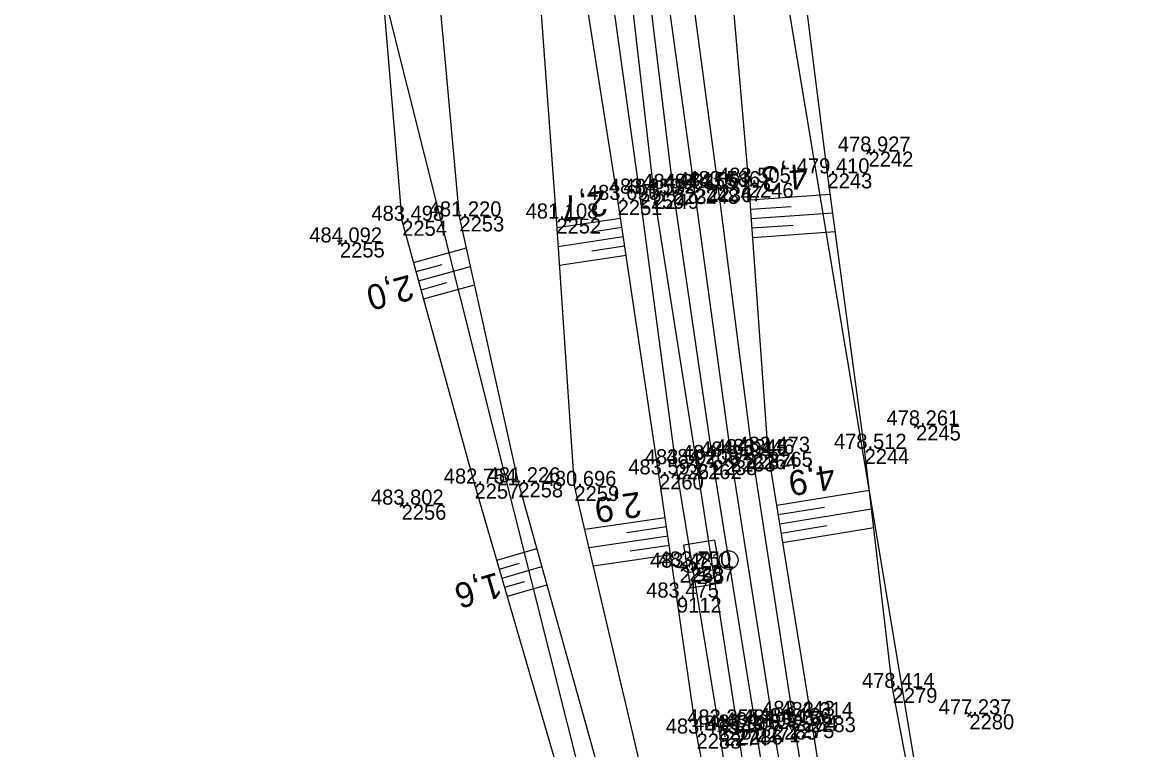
# Model space of a CAD drawing. Extents: x -1234191 to 23050, y -1290331 to -741191.
# Drawn here: x -865097.3 to -865009.1, y -1108134.3 to -1108076.3 of the extents above; entities that cross this region are included whole.
import ezdxf

# ---------------------------------------------------------------- set-up
doc = ezdxf.new("R2010")
doc.units = 0
for name, color, linetype in [('Vrstva 1', 7, 'Continuous'), ('Vrstva 4', 7, 'Continuous'), ('Vrstva 48', 7, 'Continuous'), ('Vrstva 49', 7, 'Continuous'), ('Vrstva 53', 7, 'Continuous'), ('Vrstva 60', 7, 'Continuous'), ('Vrstva 61', 7, 'Continuous'), ('Vrstva 7', 7, 'Continuous')]:
    doc.layers.add(name, color=color, linetype=linetype)

msp = doc.modelspace()

# ---------------------------------------------------------------- linework, layer by layer
at = {"layer": 'Vrstva 1'}
msp.add_lwpolyline([(-865043.737, -1107938.353), (-865046.293, -1107957.671), (-865048.446, -1107977.08), (-865049.959, -1107996.714), (-865050.615, -1108021.454), (-865049.803, -1108046.852), (-865047.929, -1108068.568), (-865045.362, -1108089.589), (-865042.206, -1108111.201), (-865038.777, -1108132.509), (-865035.865, -1108150.791), (-865033.081, -1108169.348), (-865030.656, -1108187.291), (-865028.588, -1108206.453)], dxfattribs=at)
at = {"layer": 'Vrstva 4'}
for points in [[(-865046.838, -1107937.897), (-865049.766, -1107957.319), (-865052.264, -1107976.931), (-865053.043, -1107995.978), (-865053.508, -1108021.506), (-865052.913, -1108047.234), (-865050.973, -1108068.777), (-865048.028, -1108089.964), (-865045.164, -1108111.536), (-865041.768, -1108132.286), (-865038.97, -1108150.895), (-865036.086, -1108170.021), (-865033.638, -1108187.61), (-865031.529, -1108206.589)], [(-865030.043, -1108206.47), (-865032.088, -1108187.414), (-865034.573, -1108169.592), (-865037.31, -1108151.168), (-865040.185, -1108132.688), (-865043.456, -1108111.522), (-865046.855, -1108089.973), (-865049.336, -1108068.397), (-865051.315, -1108046.93), (-865052.165, -1108021.586), (-865051.499, -1107996.614), (-865050.047, -1107977.053), (-865047.911, -1107957.568), (-865045.268, -1107938.168)], [(-865042.248, -1107938.487), (-865044.796, -1107958.232), (-865047.08, -1107977.245), (-865048.482, -1107996.693), (-865048.879, -1108021.383), (-865048.168, -1108046.692), (-865046.633, -1108068.21), (-865043.659, -1108089.569), (-865040.741, -1108110.916), (-865037.386, -1108132.285), (-865034.227, -1108151.033), (-865031.45, -1108169.147), (-865029.088, -1108187.033), (-865027.037, -1108206.108)], [(-865026.077, -1108206.153), (-865027.957, -1108186.689), (-865030.267, -1108169.011), (-865032.717, -1108150.399), (-865035.8, -1108131.6), (-865039.027, -1108110.722), (-865041.763, -1108089.361), (-865044.61, -1108068.082), (-865046.259, -1108046.615), (-865047.844, -1108021.319), (-865047.118, -1107996.694), (-865045.313, -1107977.555), (-865043.041, -1107958.531), (-865041.079, -1107938.659)]]:
    msp.add_lwpolyline(points, dxfattribs=at)
at = {"layer": 'Vrstva 48'}
for p, q in [((-865039.214, -1108090.455), (-865032.815, -1108089.998)), ((-865039.16, -1108091.203), (-865035.937, -1108090.973)), ((-865049.552, -1108091.931), (-865054.61, -1108092.693)), ((-865039.107, -1108091.951), (-865032.614, -1108091.488)), ((-865049.44, -1108092.673), (-865052, -1108093.058)), ((-865039.054, -1108092.699), (-865035.784, -1108092.466)), ((-865039, -1108093.447), (-865032.413, -1108092.977)), ((-865049.329, -1108093.414), (-865054.509, -1108094.194)), ((-865066.047, -1108095.453), (-865061.836, -1108094.293)), ((-865049.217, -1108094.156), (-865051.837, -1108094.55)), ((-865065.848, -1108096.176), (-865063.761, -1108095.601)), ((-865049.105, -1108094.897), (-865054.407, -1108095.696)), ((-865065.649, -1108096.899), (-865061.512, -1108095.76)), ((-865065.45, -1108097.622), (-865063.4, -1108097.058)), ((-865065.251, -1108098.345), (-865061.187, -1108097.226)), ((-865037.089, -1108114.803), (-865029.69, -1108113.603)), ((-865036.968, -1108115.544), (-865033.285, -1108114.946)), ((-865036.848, -1108116.284), (-865029.515, -1108115.094)), ((-865045.974, -1108115.796), (-865052.406, -1108116.735)), ((-865045.866, -1108116.538), (-865049.049, -1108117.003)), ((-865036.728, -1108117.024), (-865033.078, -1108116.432)), ((-865036.608, -1108117.765), (-865029.34, -1108116.586)), ((-865045.758, -1108117.281), (-865052.06, -1108118.2)), ((-865059.415, -1108119.178), (-865056.226, -1108118.247)), ((-865045.649, -1108118.023), (-865048.768, -1108118.478)), ((-865059.205, -1108119.898), (-865057.615, -1108119.434)), ((-865045.541, -1108118.765), (-865051.714, -1108119.666)), ((-865058.995, -1108120.618), (-865055.822, -1108119.692)), ((-865058.785, -1108121.338), (-865057.203, -1108120.876)), ((-865058.575, -1108122.058), (-865055.419, -1108121.137))]:
    msp.add_line(p, q, dxfattribs=at)
at = {"layer": 'Vrstva 49'}
for p, q in [((-865029.956, -1108086.455), (-865029.562, -1108086.763)), ((-865029.605, -1108086.412), (-865029.913, -1108086.806)), ((-865072.125, -1108093.705), (-865071.725, -1108094.003)), ((-865071.776, -1108093.654), (-865072.074, -1108094.054)), ((-865026.174, -1108108.29), (-865025.774, -1108108.588)), ((-865025.825, -1108108.239), (-865026.123, -1108108.639)), ((-865067.208, -1108114.608), (-865066.808, -1108114.906)), ((-865066.859, -1108114.557), (-865067.157, -1108114.957)), ((-865021.917, -1108131.325), (-865021.513, -1108131.619)), ((-865021.568, -1108131.27), (-865021.862, -1108131.674))]:
    msp.add_line(p, q, dxfattribs=at)
for points in [[(-865038.408, -1108186.181), (-865041.746, -1108175.265), (-865044.691, -1108155.296), (-865047.949, -1108135.607), (-865053.225, -1108113.267), (-865054.66, -1108091.943), (-865057.044, -1108059.317), (-865058.119, -1108048.868), (-865057.644, -1108021.123), (-865054.263, -1107996.365), (-865056.749, -1107976.312), (-865054.648, -1107957.542), (-865051.936, -1107936.756), (-865049.607, -1107917.984), (-865043.54, -1107878.327), (-865039.549, -1107861.727), (-865037.736, -1107845.055), (-865035.72, -1107829.325), (-865034.421, -1107813.61), (-865032.052, -1107796.735)], [(-865034.146, -1108185.382), (-865037.046, -1108170.203), (-865039.927, -1108151.218), (-865043.483, -1108133.01), (-865045.045, -1108122.164), (-865046.478, -1108112.344), (-865049.773, -1108090.463), (-865053.139, -1108069.022), (-865054.473, -1108047.375), (-865054.693, -1108021.243), (-865053.043, -1107995.978), (-865054.238, -1107976.976), (-865052.278, -1107956.977), (-865049.221, -1107937.193), (-865046.661, -1107918.236), (-865041.022, -1107878.425), (-865038.372, -1107862.082), (-865035.549, -1107845.348), (-865033.675, -1107829.555), (-865032.544, -1107813.589), (-865032.052, -1107796.735)], [(-865027.314, -1108184.355), (-865028.865, -1108168.738), (-865031.481, -1108150.159), (-865034.349, -1108131.694), (-865037.78, -1108110.54), (-865039.311, -1108089.092), (-865041.221, -1108067.079), (-865043.599, -1108046.805), (-865045.807, -1108021.331), (-865044.651, -1107996.201), (-865043.03, -1107977.831), (-865039.347, -1107959.35), (-865039.085, -1107938.119), (-865035.812, -1107919.001), (-865032.986, -1107893.483), (-865031.863, -1107879.382), (-865029.668, -1107863.423), (-865027.176, -1107846.896), (-865024.906, -1107830.539), (-865024.039, -1107813.771)], [(-865019.875, -1108184.12), (-865021.465, -1108167.421), (-865024.084, -1108149.374), (-865027.839, -1108129.369), (-865030.077, -1108110.307), (-865033.038, -1108088.344), (-865036.235, -1108062.921), (-865039.934, -1108046.29), (-865040.857, -1108022.088), (-865040.118, -1107996.004), (-865034.143, -1107980.294), (-865031.197, -1107960.331), (-865031.075, -1107928.571), (-865026.963, -1107900.752), (-865024.03, -1107878.592), (-865025.677, -1107865.45), (-865023.82, -1107848.157), (-865021.111, -1107832.183), (-865024.039, -1107813.771)], [(-865040.578, -1108188.523), (-865043.492, -1108176.04), (-865049.794, -1108152.178), (-865053.739, -1108138.634), (-865061.194, -1108113.081), (-865066.964, -1108092.124), (-865069.309, -1108064.185), (-865068.563, -1108046.185), (-865067.744, -1108018.452), (-865059.984, -1107995.159), (-865059.286, -1107975.697), (-865057.805, -1107956.237), (-865055.339, -1107936.975)], [(-865041.746, -1108175.265), (-865047.405, -1108151.931), (-865050.888, -1108137.362), (-865057.697, -1108112.978), (-865062.394, -1108091.777), (-865065.031, -1108062.839), (-865062.023, -1108047.253), (-865061.588, -1108018.947), (-865057.606, -1107991.29)]]:
    msp.add_lwpolyline(points, dxfattribs=at)
at = {"layer": 'Vrstva 53'}
for points in [[(-865097.28, -1108650.63), (-865077.79, -1108523.9), (-865062.58, -1108401.69), (-865048.74, -1108345.61), (-865033.548, -1108273.797), (-865036.719, -1108231.242), (-865042.497, -1108177.09), (-865069.37, -1108070.21), (-865060.755, -1107948.38), (-865040.047, -1107836.105), (-865031.84, -1107728.7), (-865056.26, -1107614.01)], [(-865004.69, -1107700.09), (-865003.06, -1107712.548), (-865020.95, -1107733.574), (-865021.38, -1107803.91), (-865041.945, -1107946.278), (-865044.86, -1108022.805), (-865018.158, -1108183.051), (-865018.752, -1108239.984), (-865026.02, -1108333.53), (-865033.42, -1108388.81), (-865018.239, -1108387.767), (-865021.853, -1108424.716), (-865038.93, -1108425.11), (-865057.34, -1108498.15), (-865069.183, -1108569.747)]]:
    msp.add_lwpolyline(points, dxfattribs=at)
at = {"layer": 'Vrstva 60'}
for p, q in [((-865029.759, -1108086.609), (-865029.759, -1108086.609)), ((-865033.038, -1108088.344), (-865033.038, -1108088.344)), ((-865042.613, -1108089.438), (-865042.613, -1108089.438)), ((-865041.763, -1108089.361), (-865041.763, -1108089.361)), ((-865039.311, -1108089.092), (-865039.311, -1108089.092)), ((-865048.028, -1108089.964), (-865048.028, -1108089.964)), ((-865046.855, -1108089.973), (-865046.855, -1108089.973)), ((-865045.362, -1108089.589), (-865045.362, -1108089.589)), ((-865043.659, -1108089.569), (-865043.659, -1108089.569)), ((-865049.773, -1108090.463), (-865049.773, -1108090.463)), ((-865066.964, -1108092.124), (-865066.964, -1108092.124)), ((-865062.394, -1108091.777), (-865062.394, -1108091.777)), ((-865054.66, -1108091.943), (-865054.66, -1108091.943)), ((-865071.925, -1108093.854), (-865071.925, -1108093.854)), ((-865025.974, -1108108.439), (-865025.974, -1108108.439)), ((-865037.78, -1108110.54), (-865037.78, -1108110.54)), ((-865030.077, -1108110.307), (-865030.077, -1108110.307)), ((-865045.164, -1108111.536), (-865045.164, -1108111.536)), ((-865043.456, -1108111.522), (-865043.456, -1108111.522)), ((-865042.206, -1108111.201), (-865042.206, -1108111.201)), ((-865040.741, -1108110.916), (-865040.741, -1108110.916)), ((-865039.55, -1108110.739), (-865039.55, -1108110.739)), ((-865039.027, -1108110.722), (-865039.027, -1108110.722)), ((-865046.478, -1108112.344), (-865046.478, -1108112.344)), ((-865061.194, -1108113.081), (-865061.194, -1108113.081)), ((-865057.697, -1108112.978), (-865057.697, -1108112.978)), ((-865053.225, -1108113.267), (-865053.225, -1108113.267)), ((-865067.008, -1108114.757), (-865067.008, -1108114.757)), ((-865044.838, -1108119.782), (-865044.838, -1108119.782)), ((-865044.058, -1108119.683), (-865044.058, -1108119.683)), ((-865045.045, -1108122.164), (-865045.045, -1108122.164)), ((-865027.839, -1108129.369), (-865027.839, -1108129.369)), ((-865035.8, -1108131.6), (-865035.8, -1108131.6)), ((-865034.349, -1108131.694), (-865034.349, -1108131.694)), ((-865021.715, -1108131.472), (-865021.715, -1108131.472)), ((-865041.768, -1108132.286), (-865041.768, -1108132.286)), ((-865040.185, -1108132.688), (-865040.185, -1108132.688)), ((-865038.777, -1108132.509), (-865038.777, -1108132.509)), ((-865037.386, -1108132.285), (-865037.386, -1108132.285)), ((-865036.059, -1108132.169), (-865036.059, -1108132.169)), ((-865043.483, -1108133.01), (-865043.483, -1108133.01)), ((-865041.306, -1108132.768), (-865041.306, -1108132.768))]:
    msp.add_line(p, q, dxfattribs=at)
at = {"layer": 'Vrstva 7'}
for p, q in [((-865042.118, -1108089.366), (-865043.108, -1108089.51)), ((-865042.685, -1108088.943), (-865042.541, -1108089.933)), ((-865039.055, -1108110.667), (-865040.045, -1108110.811)), ((-865039.622, -1108110.244), (-865039.478, -1108111.234)), ((-865044.838, -1108119.782), (-865044.223, -1108119.683)), ((-865044.066, -1108119.634), (-865044.05, -1108119.732)), ((-865036.138, -1108131.675), (-865035.98, -1108132.663)), ((-865040.812, -1108132.689), (-865041.8, -1108132.847)), ((-865041.385, -1108132.274), (-865041.227, -1108133.262)), ((-865035.565, -1108132.09), (-865036.553, -1108132.248))]:
    msp.add_line(p, q, dxfattribs=at)
msp.add_lwpolyline([(-865044.5, -1108117.963), (-865042.048, -1108117.569), (-865041.494, -1108121.012), (-865043.946, -1108121.407)], close=True, dxfattribs=at)
for centre, radius in [((-865040.922, -1108119.178), 0.75), ((-865044.058, -1108119.683), 0.5)]:
    msp.add_circle(centre, radius, dxfattribs=at)

# ---------------------------------------------------------------- texts
at = {"layer": 'Vrstva 48'}
for s, rotation, p in [('4,3', 184.08296, (-865034.681, -1108087.576)), ('2,7', 188.56367, (-865050.76, -1108089.671)), ('2,0', 195.3936, (-865066.392, -1108096.406)), ('4,9', 189.21267, (-865032.604, -1108111.523)), ('2,9', 188.30238, (-865048.047, -1108113.718)), ('1,6', 196.26442, (-865059.376, -1108120.124))]:
    msp.add_text(s, height=2, rotation=rotation, dxfattribs=at).set_placement(p)
at = {"layer": 'Vrstva 60'}
for s, p in [('2242', (-865029.759, -1108087.809)), ('2243', (-865033.038, -1108089.544)), ('2236', (-865042.613, -1108090.638)), ('2247', (-865041.763, -1108090.561)), ('2246', (-865039.311, -1108090.292)), ('2250', (-865048.028, -1108091.164)), ('2249', (-865046.855, -1108091.173)), ('2234', (-865045.362, -1108090.789)), ('2248', (-865043.659, -1108090.769)), ('2251', (-865049.773, -1108091.663)), ('2254', (-865066.964, -1108093.324)), ('2253', (-865062.394, -1108092.977)), ('2252', (-865054.66, -1108093.143)), ('2255', (-865071.925, -1108095.054)), ('2245', (-865025.974, -1108109.639)), ('2264', (-865039.027, -1108111.922)), ('2265', (-865037.78, -1108111.74)), ('2244', (-865030.077, -1108111.507)), ('2261', (-865045.164, -1108112.736)), ('2262', (-865043.456, -1108112.722)), ('2238', (-865042.206, -1108112.401)), ('2263', (-865040.741, -1108112.116)), ('2237', (-865039.55, -1108111.939)), ('2260', (-865046.478, -1108113.544)), ('2257', (-865061.194, -1108114.281)), ('2258', (-865057.697, -1108114.178)), ('2259', (-865053.225, -1108114.467)), ('2256', (-865067.008, -1108115.957)), ('2268', (-865044.838, -1108120.982)), ('2267', (-865044.058, -1108120.883)), ('9112', (-865045.045, -1108123.364)), ('2279', (-865027.839, -1108130.569)), ('2284', (-865035.8, -1108132.8)), ('2283', (-865034.349, -1108132.894)), ('2280', (-865021.715, -1108132.672)), ('2287', (-865041.768, -1108133.486)), ('2274', (-865041.306, -1108133.968)), ('2286', (-865040.185, -1108133.888)), ('2271', (-865038.777, -1108133.709)), ('2285', (-865037.386, -1108133.485)), ('2275', (-865036.059, -1108133.369)), ('2288', (-865043.483, -1108134.21))]:
    msp.add_text(s, height=1.2, dxfattribs=at).set_placement(p)
at = {"layer": 'Vrstva 61'}
for s, p in [('478.927', (-865032.211, -1108086.609)), ('479.410', (-865035.489, -1108088.344)), ('484.634', (-865047.813, -1108089.589)), ('484.355', (-865046.115, -1108089.569)), ('484.561', (-865044.97, -1108089.438)), ('483.586', (-865044.215, -1108089.361)), ('483.505', (-865041.767, -1108089.092)), ('483.690', (-865052.224, -1108090.463)), ('483.959', (-865050.482, -1108089.964)), ('484.532', (-865049.303, -1108089.973)), ('483.498', (-865069.418, -1108092.124)), ('481.220', (-865064.845, -1108091.777)), ('481.108', (-865057.114, -1108091.943)), ('484.092', (-865074.373, -1108093.854)), ('478.261', (-865028.331, -1108108.439)), ('484.194', (-865043.192, -1108110.916)), ('484.345', (-865042.006, -1108110.739)), ('483.446', (-865041.479, -1108110.722)), ('483.473', (-865040.232, -1108110.54)), ('478.512', (-865032.525, -1108110.307)), ('483.592', (-865047.612, -1108111.536)), ('484.208', (-865045.91, -1108111.522)), ('484.392', (-865044.654, -1108111.201)), ('483.593', (-865048.93, -1108112.344)), ('482.754', (-865063.645, -1108113.081)), ('481.226', (-865060.149, -1108112.978)), ('480.696', (-865055.677, -1108113.267)), ('483.802', (-865069.456, -1108114.757)), ('483.421', (-865047.195, -1108119.782)), ('483.750', (-865046.509, -1108119.683)), ('483.475', (-865047.501, -1108122.164)), ('478.414', (-865030.29, -1108129.369)), ('484.136', (-865038.511, -1108132.169)), ('483.443', (-865038.252, -1108131.6)), ('483.314', (-865036.8, -1108131.694)), ('477.237', (-865024.167, -1108131.472)), ('483.475', (-865045.939, -1108133.01)), ('483.355', (-865044.224, -1108132.286)), ('484.119', (-865043.76, -1108132.768)), ('483.986', (-865042.637, -1108132.688)), ('484.199', (-865041.231, -1108132.509)), ('484.043', (-865039.838, -1108132.285))]:
    msp.add_text(s, height=1.2, dxfattribs=at).set_placement(p)
at = {"layer": 'Vrstva 7'}
msp.add_text('KM', height=1.2469, rotation=279.14197, dxfattribs=at).set_placement((-865043.773, -1108118.581))

doc.saveas('drawing.dxf')
